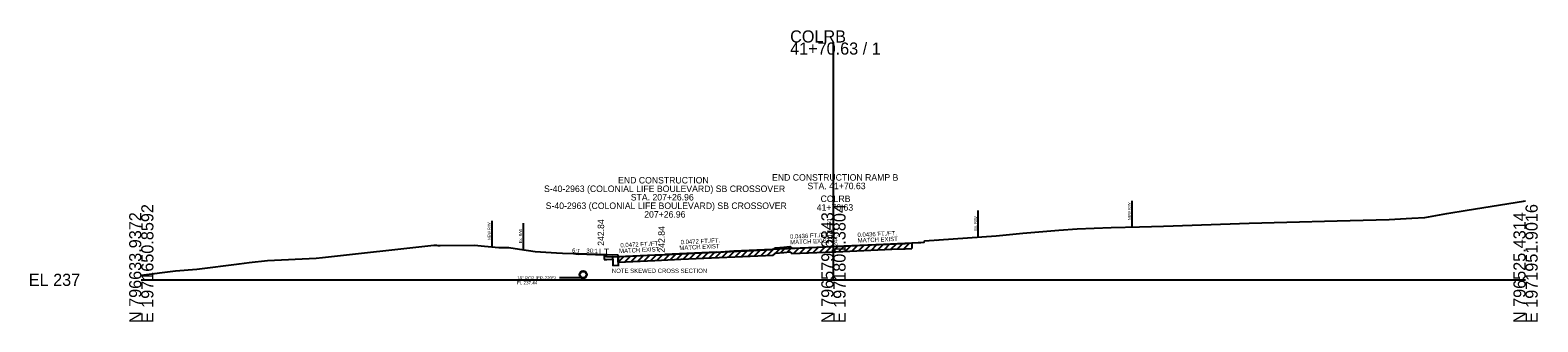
# Model space of a CAD drawing. Extents: x -26 to 1971766, y -10 to 796432.
# Drawn here: x -25.7 to 322.8, y 6490.3 to 6557.6 of the extents above; entities that cross this region are included whole.
import ezdxf

# ---------------------------------------------------------------- set-up
doc = ezdxf.new("R2010")
doc.units = 0
for name, color, linetype in [('BR_AUTO DIMENSION', 7, 'Continuous'), ('BR_BORDER LINES', 7, 'Continuous'), ('BR_CENTER LINE BASELINE', 7, 'Continuous'), ('BR_CONCRETE', 7, 'Continuous'), ('BR_PRESTRESSED BEAM', 7, 'Continuous'), ('BR_REBAR', 7, 'Continuous'), ('BR_TABLE LINES', 7, 'Continuous'), ('Level 31', 7, 'Continuous'), ('MISCELLANEOUS', 7, 'Continuous'), ('North Arrow', 7, 'Continuous'), ('RD_EX_Conc', 7, 'Continuous'), ('RD_EX_Road', 7, 'Continuous'), ('RD_HC_CL_Rel', 7, 'Continuous'), ('RD_PD_ALT2_TnTmp', 7, 'Continuous'), ('RD_PD_CstnLmt', 7, 'Continuous'), ('RD_PD_Final_LnLine', 7, 'Continuous'), ('RD_PD_Final_TrvlWay', 7, 'Continuous'), ('RD_PD_FOC', 7, 'Continuous'), ('RD_PD_MedBWall', 7, 'Continuous'), ('RD_PD_WallFill', 7, 'Continuous'), ('RD_SHT_IplotShp', 7, 'Continuous')]:
    doc.layers.add(name, color=color, linetype=linetype)

msp = doc.modelspace()

# ---------------------------------------------------------------- linework, layer by layer
at = {"layer": 'BR_AUTO DIMENSION'}
for p, q in [((160, 6500), (160, 6554.78)), ((0, 6500), (160, 6500)), ((160, 6500), (320, 6500))]:
    msp.add_line(p, q, dxfattribs=at)
at = {"layer": 'BR_BORDER LINES'}
msp.add_lwpolyline([(0, 6501.1), (7.9, 6502.07), (12.8, 6502.49), (22.59, 6503.72), (23.76, 6503.82), (24.97, 6503.96), (29.16, 6504.46), (40.42, 6505.02), (41.86, 6505.13), (67.64, 6507.97), (68.21, 6507.96), (68.55, 6507.94), (69.08, 6507.92), (77.04, 6507.97), (79.3, 6507.73), (82.68, 6507.47), (84.95, 6507.47), (87.45, 6507.05), (91.02, 6506.54), (96, 6506.23), (97.35, 6506.12), (100.64, 6506.07), (110.1, 6505.73), (110.26, 6505.36), (118.7, 6505.73), (120.23, 6505.8), (124.69, 6506), (146.09, 6506.97), (146.57, 6507.37), (148.55, 6507.55), (149.9, 6507.69), (150.38, 6507.29), (160, 6507.71), (160.54, 6507.73), (173.5, 6508.3), (176.58, 6508.42), (178.15, 6508.5), (180.2, 6508.65), (180.95, 6508.7), (181.02, 6508.98), (197.6, 6510.19), (203.75, 6510.76), (212.13, 6511.43), (216.33, 6511.79), (224.21, 6512.05), (230.75, 6512.26), (236.3, 6512.39), (256.12, 6513.06), (264.83, 6513.32), (276.46, 6513.63), (288.44, 6513.92), (293.68, 6514.2), (296.72, 6514.4), (301.83, 6515.34), (306.51, 6516.04), (319.51, 6518.19), (320, 6518.26)], dxfattribs=at)
at = {"layer": 'BR_CENTER LINE BASELINE'}
for p, q in [((173.5, 6507.05), (176.58, 6507.17)), ((176.58, 6507.17), (178.15, 6507.25)), ((178.15, 6508.5), (178.15, 6507.25)), ((110.26, 6504.11), (110.26, 6505.36)), ((110.26, 6504.11), (118.7, 6504.48)), ((118.7, 6504.48), (120.23, 6504.55)), ((120.23, 6504.55), (124.69, 6504.75)), ((124.69, 6504.75), (146.09, 6505.72)), ((146.09, 6505.72), (146.57, 6506.12)), ((146.57, 6506.12), (148.55, 6506.3)), ((148.55, 6506.3), (149.9, 6506.44)), ((149.9, 6506.44), (150.38, 6506.04)), ((150.38, 6506.04), (160, 6506.46)), ((160, 6506.46), (160.54, 6506.48)), ((160.54, 6506.48), (173.5, 6507.05))]:
    msp.add_line(p, q, dxfattribs=at)
at = {"layer": 'BR_PRESTRESSED BEAM'}
for p, q in [((107, 6505.7), (107, 6504.7)), ((107, 6504.7), (107.58, 6504.7)), ((107.58, 6504.7), (109, 6504.77))]:
    msp.add_line(p, q, dxfattribs=at)
at = {"layer": 'BR_TABLE LINES'}
for p, q in [((193.42, 6515.98), (193.42, 6509.98)), ((88.24, 6513.08), (88.24, 6507.08))]:
    msp.add_line(p, q, dxfattribs=at)
at = {"layer": 'Level 31'}
for p, q in [((146.27, 6505.87), (147.89, 6507.49)), ((147.77, 6506.23), (149.14, 6507.61)), ((149.27, 6506.37), (150.27, 6507.38)), ((150.77, 6506.05), (152.07, 6507.36)), ((152.27, 6506.12), (153.57, 6507.43)), ((153.77, 6506.18), (155.07, 6507.49)), ((155.27, 6506.25), (156.57, 6507.56)), ((156.77, 6506.32), (158.07, 6507.62)), ((158.27, 6506.38), (159.57, 6507.69)), ((159.77, 6506.45), (161.07, 6507.76)), ((161.27, 6506.51), (162.57, 6507.82)), ((162.77, 6506.58), (164.07, 6507.89)), ((164.27, 6506.64), (165.57, 6507.95)), ((165.77, 6506.71), (167.07, 6508.02)), ((167.27, 6506.78), (168.57, 6508.08)), ((168.77, 6506.84), (170.07, 6508.15)), ((170.27, 6506.91), (171.57, 6508.21)), ((171.77, 6506.97), (173.07, 6508.28)), ((173.27, 6507.04), (174.57, 6508.34)), ((174.77, 6507.1), (176.07, 6508.4)), ((176.27, 6507.16), (177.58, 6508.47)), ((110.26, 6504.11), (111.57, 6505.42)), ((111.76, 6504.18), (113.07, 6505.48)), ((113.26, 6504.24), (114.57, 6505.55)), ((114.76, 6504.31), (116.07, 6505.61)), ((116.26, 6504.37), (117.57, 6505.68)), ((117.76, 6504.44), (119.07, 6505.75)), ((119.26, 6504.5), (120.57, 6505.82)), ((120.76, 6504.57), (122.07, 6505.88)), ((122.26, 6504.64), (123.57, 6505.95)), ((123.76, 6504.71), (125.07, 6506.02)), ((125.26, 6504.78), (126.57, 6506.09)), ((126.76, 6504.85), (128.07, 6506.16)), ((128.26, 6504.92), (129.57, 6506.22)), ((129.76, 6504.98), (131.07, 6506.29)), ((131.26, 6505.05), (132.57, 6506.36)), ((132.76, 6505.12), (134.07, 6506.43)), ((134.26, 6505.19), (135.57, 6506.5)), ((135.76, 6505.26), (137.07, 6506.56)), ((137.26, 6505.32), (138.57, 6506.63)), ((138.76, 6505.39), (140.07, 6506.7)), ((140.26, 6505.46), (141.57, 6506.77)), ((141.76, 6505.53), (143.07, 6506.84)), ((143.27, 6505.6), (144.57, 6506.9)), ((144.77, 6505.66), (146.07, 6506.97))]:
    msp.add_line(p, q, dxfattribs=at)
at = {"layer": 'MISCELLANEOUS'}
for p, q in [((146.09, 6506.97), (146.57, 6507.37)), ((146.57, 6507.37), (148.55, 6507.55)), ((148.55, 6507.55), (149.9, 6507.69)), ((149.9, 6507.69), (150.38, 6507.29)), ((150.38, 6507.29), (160, 6507.71)), ((160, 6507.71), (160.54, 6507.73)), ((160.54, 6507.73), (173.5, 6508.3)), ((173.5, 6508.3), (175.9, 6508.39)), ((110.26, 6505.36), (118.7, 6505.73)), ((110.26, 6505.15), (110.26, 6503.16)), ((118.7, 6505.73), (120.23, 6505.8)), ((120.23, 6505.8), (124.69, 6506)), ((124.69, 6506), (146.09, 6506.97))]:
    msp.add_line(p, q, dxfattribs=at)
at = {"layer": 'North Arrow'}
for p, q in [((137, 6506.71), (160, 6507.71)), ((160, 6507.71), (178.15, 6508.5)), ((160, 6507.71), (175.9, 6508.4)), ((178.15, 6508.5), (180.95, 6508.7)), ((109, 6505.27), (121, 6505.84)), ((133, 6506.4), (121, 6505.84))]:
    msp.add_line(p, q, dxfattribs=at)
at = {"layer": 'RD_EX_Conc'}
for p, q in [((107.5, 6505.7), (107, 6505.7)), ((107.58, 6505.2), (107.5, 6505.7)), ((109, 6505.27), (107.58, 6505.2)), ((109, 6505.15), (109, 6505.13))]:
    msp.add_line(p, q, dxfattribs=at)
at = {"layer": 'RD_EX_Road'}
for p, q in [((109, 6504.77), (109, 6505.27)), ((109, 6505.13), (109, 6505.15)), ((109, 6504.77), (109, 6503.25)), ((110.26, 6503.31), (109, 6503.25))]:
    msp.add_line(p, q, dxfattribs=at)
at = {"layer": 'RD_PD_CstnLmt'}
for p, q in [((228.99, 6518.2), (228.99, 6512.2)), ((81, 6513.6), (81, 6507.6))]:
    msp.add_line(p, q, dxfattribs=at)
at = {"layer": 'RD_PD_Final_LnLine'}
for p, q in [((183.9, 6509.14), (184.42, 6509.23)), ((99.89, 6506.08), (101, 6505.9)), ((107, 6505.7), (101, 6505.9))]:
    msp.add_line(p, q, dxfattribs=at)
at = {"layer": 'RD_PD_FOC'}
msp.add_line((101.64, 6500.44), (96.64, 6500.44), dxfattribs=at)
for radius in [0.85, 0.75]:
    msp.add_circle((102.14, 6501.19), radius, dxfattribs=at)
at = {"layer": 'RD_PD_MedBWall'}
msp.add_line((133, 6506.4), (137, 6506.71), dxfattribs=at)

# ---------------------------------------------------------------- texts
at = {"layer": 'BR_AUTO DIMENSION'}
for s, p in [('COLRB', (150, 6554.78)), ('41+70.63 / 1', (150, 6551.98)), ('EL 237', (-26, 6498.6))]:
    msp.add_text(s, height=2.8, dxfattribs=at).set_placement(p)
for s, p in [('N 796633.9372', (0, 6490)), ('E 1971650.8592', (2.8, 6490)), ('N 796579.6843', (160, 6490)), ('E 1971801.3804', (162.8, 6490)), ('N 796525.4314', (320, 6490)), ('E 1971951.9016', (322.8, 6490))]:
    msp.add_text(s, height=2.8, rotation=90, dxfattribs=at).set_placement(p)
at = {"layer": 'BR_CONCRETE'}
for s, rotation, p in [('0.0436 FT./FT.', 2.4965, (149.98, 6509.49)), ('0.0436 FT./FT.', 2.4965, (165.58, 6509.89)), ('6:1', 350.5377, (99.49, 6506.36)), ('30:1', 358.0908, (102.88, 6506.23)), ('MATCH EXIST', 2.7024, (110.47, 6506.15)), ('0.0472 FT./FT.', 2.7024, (110.77, 6507.48)), ('MATCH EXIST', 2.7024, (124.41, 6506.87)), ('0.0472 FT./FT.', 2.7024, (124.7, 6508.2)), ('MATCH EXIST', 2.4965, (150.03, 6508.18)), ('MATCH EXIST', 2.4965, (165.63, 6508.58))]:
    msp.add_text(s, height=1, rotation=rotation, dxfattribs=at).set_placement(p)
at = {"layer": 'BR_REBAR'}
msp.add_text('LT', height=1.5, dxfattribs=at).set_placement((105.8, 6505.7))
at = {"layer": 'BR_TABLE LINES'}
for p in [(193.17, 6511.37), (87.99, 6508.46)]:
    msp.add_text('Ex. R/W ', height=0.65, rotation=90, dxfattribs=at).set_placement(p)
at = {"layer": 'RD_HC_CL_Rel'}
for s, p in [(' 244.71', (160, 6507.71)), (' 242.84', (121, 6505.71))]:
    msp.add_text(s, height=1.5, rotation=90, dxfattribs=at).set_placement(p)
at = {"layer": 'RD_PD_ALT2_TnTmp'}
for s, height, p in [('S-40-2963 (COLONIAL LIFE BOULEVARD) SB CROSSOVER', 1.5, (93.11, 6520.27)), ('END CONSTRUCTION', 1.5, (110.22, 6522.24)), ('END CONSTRUCTION RAMP B', 1.5, (145.81, 6522.89)), ('STA. 41+70.63', 1.5, (154, 6520.92)), ('STA. 207+26.96', 1.5, (113.15, 6518.31)), ('NOTE SKEWED CROSS SECTION', 1, (108.79, 6501.58))]:
    msp.add_text(s, height=height, dxfattribs=at).set_placement(p)
at = {"layer": 'RD_PD_CstnLmt'}
for p in [(228.73, 6513.76), (80.73, 6509.16)]:
    msp.add_text('NEW R/W ', height=0.65, rotation=90, dxfattribs=at).set_placement(p)
at = {"layer": 'RD_PD_Final_TrvlWay'}
msp.add_text('242.84', height=1.5, rotation=90, dxfattribs=at).set_placement((107, 6507.84))
at = {"layer": 'RD_PD_FOC'}
for s, p in [('18" RCP (EP-2205)', (86.87, 6500.06)), ('FL 237.44', (86.87, 6498.94))]:
    msp.add_text(s, height=0.75, dxfattribs=at).set_placement(p)
at = {"layer": 'RD_PD_WallFill'}
for s, p in [('S-40-2963 (COLONIAL LIFE BOULEVARD) SB CROSSOVER', (93.49, 6516.35)), ('COLRB', (157.03, 6517.96)), ('207+26.96', (116.26, 6514.35)), ('41+70.63', (156.14, 6515.96))]:
    msp.add_text(s, height=1.5, dxfattribs=at).set_placement(p)
at = {"layer": 'RD_SHT_IplotShp'}
msp.add_text('244.71', height=1, rotation=90, dxfattribs=at).set_placement((161, 6507.71))

doc.saveas('drawing.dxf')
